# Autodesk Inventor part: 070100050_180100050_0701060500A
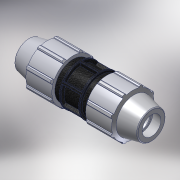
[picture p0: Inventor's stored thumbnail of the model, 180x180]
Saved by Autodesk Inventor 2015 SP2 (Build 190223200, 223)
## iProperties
Created: 2017-02
Part Number: 070100050_180100050_0701060500A
Material: PVC-Piping
Description: PLASSON COUPLER 50-50
Document SubType Name: Modeling
Designer: KIM
Mass: 92.6774 g
Surface Area: 199.44 cm^2
Volume: 66.1981 cm^3
Density: 1.4 g/cm^3
Appearance: PTFE
Author: KIM
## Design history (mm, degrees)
derived "07010.ipt"
feature "Solid1::07010.ipt"
tag "TaggingFeature1"
body "Solid1"
other parameters: "d1" = 201, "d4" = 16.75, "d5" = 28.71429, "d7" = 96, "d8" = 72, "d9" = 28.71429, "d11" = 2.87143, "d12" = 76.8, "d13" = 120 deg, "d14" = 75, "d15" = 8 deg, "d16" = 86.4, "d18" = 2.5, "d19" = 35 deg, "d20" = 17.5 deg, "d21" = 89.28, "d23" = 0, "d25" = 360 deg, "d27" = 1.92, "d33" = 1, "d34" = 4.8, "d36" = 0, "d37" = 1, "d38" = 1, "d40" = 360 deg, "d42" = 44.22, "d43" = 2.88, "d46" = 1.5, "d49" = 98, "E_" = 96, "H_" = 201, "l_" = 98
